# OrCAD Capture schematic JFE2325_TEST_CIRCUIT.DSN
size A; title: JFE2325 Dual, Low-Power, N-Channel JFET for Electret Microphones; rev: 1.0; note: DS: SLPS816A - MAY 2026  EVM: SLUVDC6 - NOV 2025
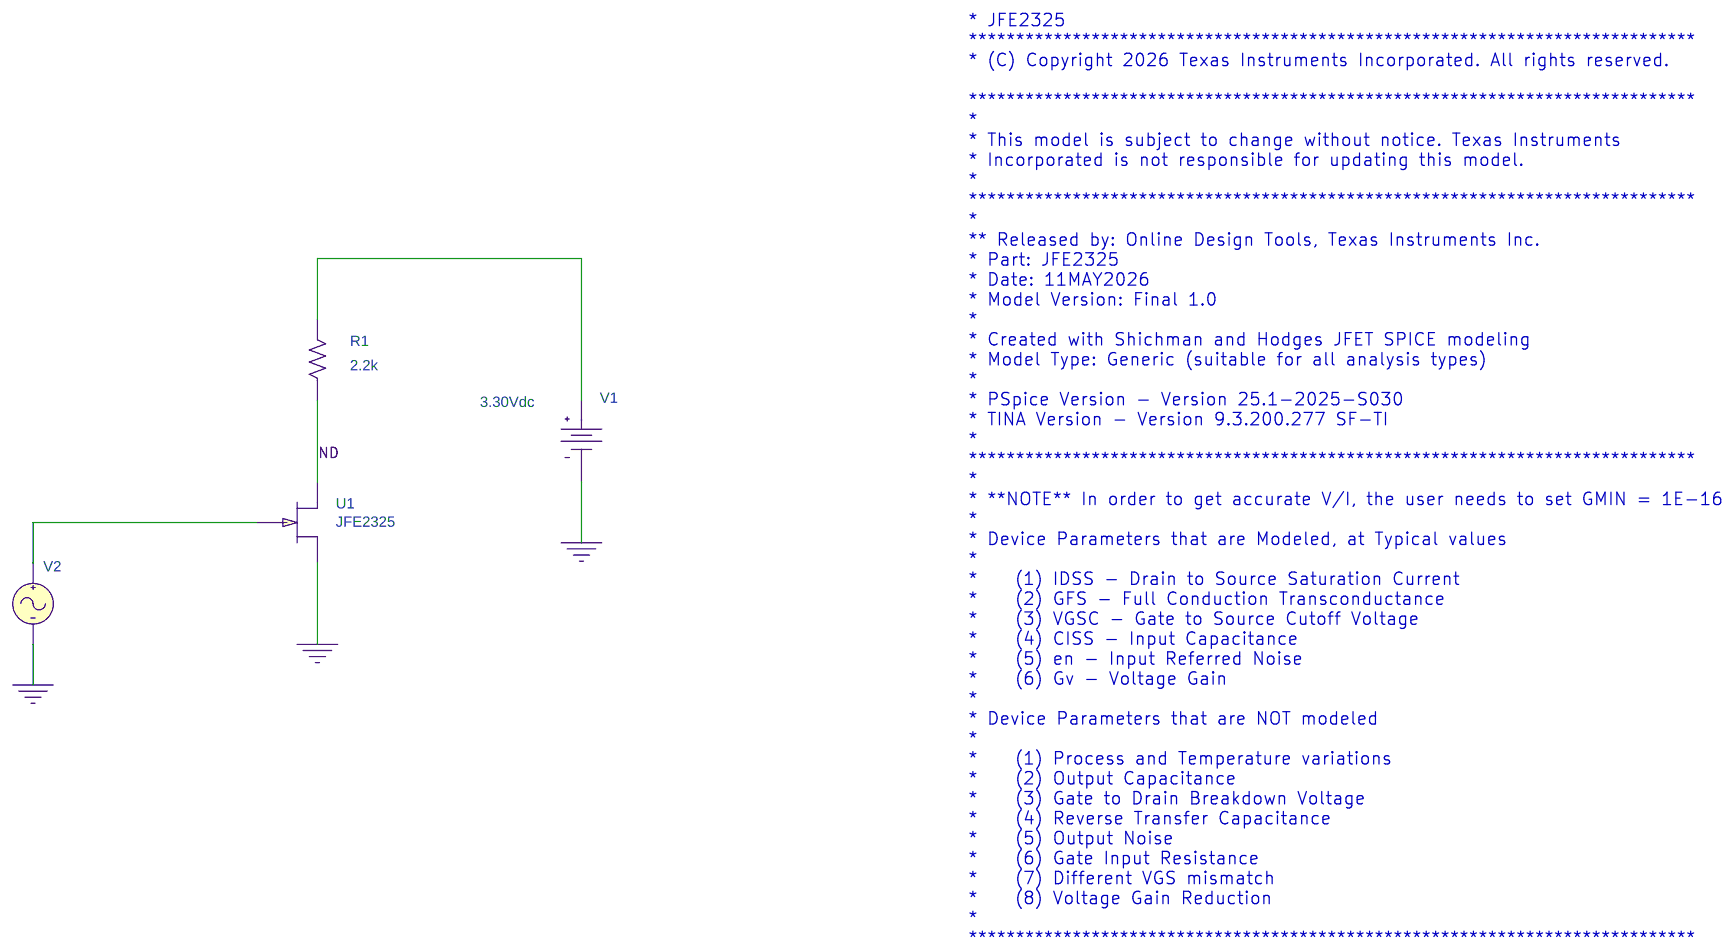
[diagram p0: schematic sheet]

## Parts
R1  2.2k  [AXRC05]
U1  JFE2325
V1  VDC
V2  VAC

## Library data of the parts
R1 = R
U1 = JFE2325
V1 = VDC: DC: 3.30Vdc
V2 = VAC

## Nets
0: U1.3(SOURCE) V1.1(-) V2.2(-)
ND: R1.1 U1.2(DRAIN)
N00173: R1.2 V1.0(+)
N00189: U1.1(GATE) V2.1(+)

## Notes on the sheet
- * JFE2325
  *****************************************************************************
  * (C) Copyright 2026 Texas Instruments Incorporated. All rights reserved.
  *****************************************************************************
  *
  * This model is subject to change without notice. Texas Instruments
  * Incorporated is not responsible for updating this model.
  *
  *****************************************************************************
  *
  ** Released by: Online Design Tools, Texas Instruments Inc.
  * Part: JFE2325
  * Date: 11MAY2026
  * Model Version: Final 1.0
  *
  * Created with Shichman and Hodges JFET SPICE modeling
  * Model Type: Generic (suitable for all analysis types)
  *
  * PSpice Version - Version 25.1-2025-S030
  * TINA Version - Version 9.3.200.277 SF-TI
  *
  *****************************************************************************
  *
  * **NOTE** In order to get accurate V/I, the user needs to set GMIN = 1E-16
  *
  * Device Parameters that are Modeled, at Typical values
  *
  *	(1) IDSS - Drain to Source Saturation Current
  *	(2) GFS - Full Conduction Transconductance
  *	(3) VGSC - Gate to Source Cutoff Voltage
  *	(4) CISS - Input Capacitance
  *	(5) en - Input Referred Noise
  *	(6) Gv - Voltage Gain
  *
  * Device Parameters that are NOT modeled
  *
  *	(1) Process and Temperature variations
  *	(2) Output Capacitance
  *	(3) Gate to Drain Breakdown Voltage
  *	(4) Reverse Transfer Capacitance
  *	(5) Output Noise
  *	(6) Gate Input Resistance
  *	(7) Different VGS mismatch
  *	(8) Voltage Gain Reduction
  *
  *****************************************************************************
